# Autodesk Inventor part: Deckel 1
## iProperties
Created: 2006-11
Part Number: Deckel 1
Document SubType Name: Blech
Designer: User
Material: Edelstahl
Author: User
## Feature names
1. Erhebung1
2. Wandstärke1
